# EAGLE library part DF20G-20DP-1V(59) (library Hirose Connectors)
CONN, VERT, SMT, 20 POS, 5x2, 1MM, GOLD, W/O BOSS (HIROSE)
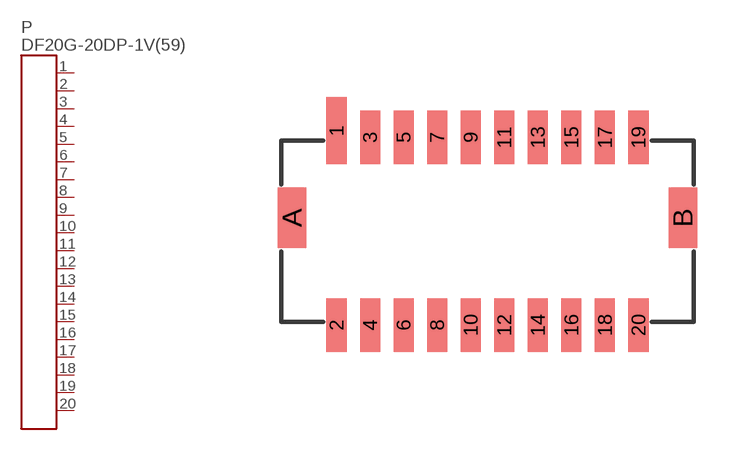
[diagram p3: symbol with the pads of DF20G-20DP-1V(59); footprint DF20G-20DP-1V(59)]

Designator prefix P

## DF20G-20DP-1V(59)  [DF20G-20DP-1V(59)]
1  P$1
2  P$2
3  P$3
4  P$4
5  P$5
6  P$6
7  P$7
8  P$8
9  P$9
10  P$10
11  P$11
12  P$12
13  P$13
14  P$14
15  P$15
16  P$16
17  P$17
18  P$18
19  P$19
20  P$20

## Footprint DF20G-20DP-1V(59) (pad centres in mm)
smd 0.6 x 2: 1 -4.5,3
smd 0.6 x 1.6: 2 -4.5,-2.8; 3 -3.5,2.8; 4 -3.5,-2.8; 5 -2.5,2.8; 6 -2.5,-2.8; 7 -1.5,2.8; 8 -1.5,-2.8; 9 -0.5,2.8; 10 -0.5,-2.8; 11 0.5,2.8; 12 0.5,-2.8; 13 1.5,2.8; 14 1.5,-2.8; 15 2.5,2.8; 16 2.5,-2.8; 17 3.5,2.8; 18 3.5,-2.8; 19 4.5,2.8; 20 4.5,-2.8
smd 0.85 x 1.8: A -5.825,0.4; B 5.825,0.4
